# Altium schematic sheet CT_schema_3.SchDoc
size 282 x 169 mm
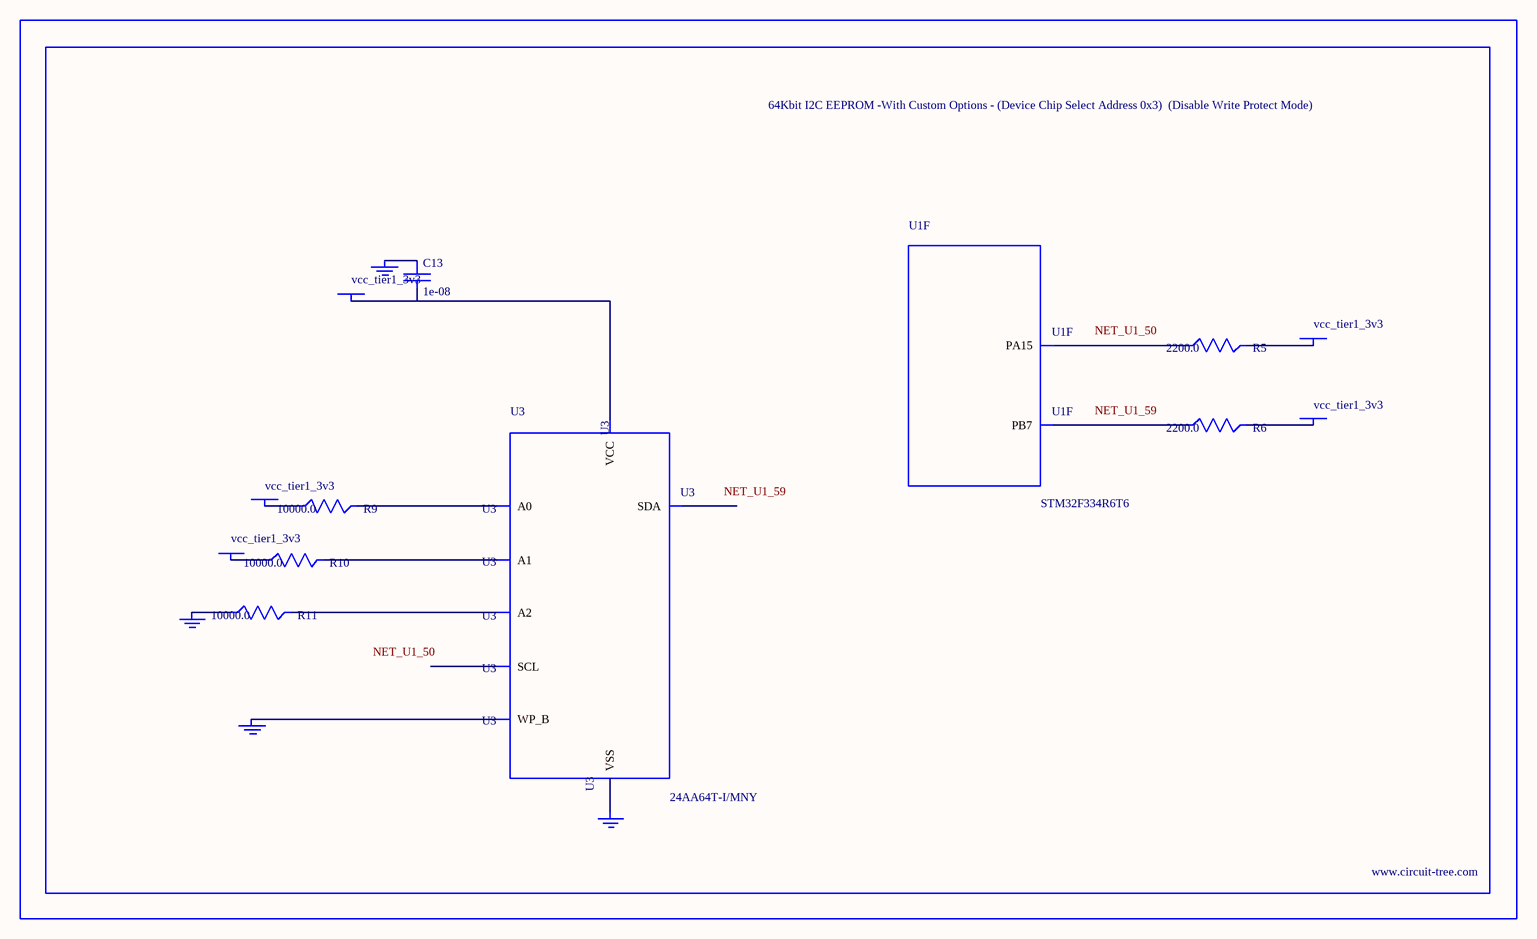
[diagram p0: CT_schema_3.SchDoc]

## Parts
BORDER2  (no value)
C13  1e-08  [C0402]
GND_INSTANCE_2_0  (no value)
GND_INSTANCE_2_1  (no value)
GND_INSTANCE_2_2  (no value)
GND_INSTANCE_2_3  (no value)
POWER_INSTANCE_2_0  vcc_tier1_3v3
POWER_INSTANCE_2_1  vcc_tier1_3v3
POWER_INSTANCE_2_2  vcc_tier1_3v3
POWER_INSTANCE_2_3  vcc_tier1_3v3
POWER_INSTANCE_2_4  vcc_tier1_3v3
R5  2200.0  [R0603]
R6  2200.0  [R0603]
R9  10000.0  [R0603]
R10  10000.0  [R0603]
R11  10000.0  [R0603]
U1  STM32F334R6T6  [LQFP64]  (part F of 7)
U3  24AA64T-I/MNY  [TDFN-8/6MM]

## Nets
NetC13_1: C13.1 GND_INSTANCE_2_2.0(GND)
NetC13_2: C13.2 POWER_INSTANCE_2_2.0(PWR) U3.8(VCC)
NetGND_INSTANCE_2_0_0: GND_INSTANCE_2_0.0(GND) R11.1
NetGND_INSTANCE_2_1_0: GND_INSTANCE_2_1.0(GND) U3.7(WP_B)
NetGND_INSTANCE_2_3_0: GND_INSTANCE_2_3.0(GND) U3.4(VSS)
NetPOWER_INSTANCE_2_0_0: POWER_INSTANCE_2_0.0(PWR) R9.1
NetPOWER_INSTANCE_2_1_0: POWER_INSTANCE_2_1.0(PWR) R10.1
NetPOWER_INSTANCE_2_3_0: POWER_INSTANCE_2_3.0(PWR) R5.2
NetPOWER_INSTANCE_2_4_0: POWER_INSTANCE_2_4.0(PWR) R6.2
NetR5_1: R5.1 U1.50(PA15)
NetR6_1: R6.1 U1.59(PB7)
NetR9_2: R9.2 U3.1(A0)
NetR10_2: R10.2 U3.2(A1)
NetR11_2: R11.2 U3.3(A2)

Not connected (* = marked no-connect by the designer): U3 5(SDA) 6(SCL)

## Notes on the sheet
- Labels drawn without touching a wire or pin: NET_U1_50, NET_U1_59

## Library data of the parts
BORDER2 = BORDER_PAGE2
C13 = C0402C103K3RAC
GND_INSTANCE_2_0-GND_INSTANCE_2_3 = GND
POWER_INSTANCE_2_0-POWER_INSTANCE_2_4 = PWR
R5 R6 = RC0603JR-072K2L
R9-R11 = RC0603JR-0710KL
